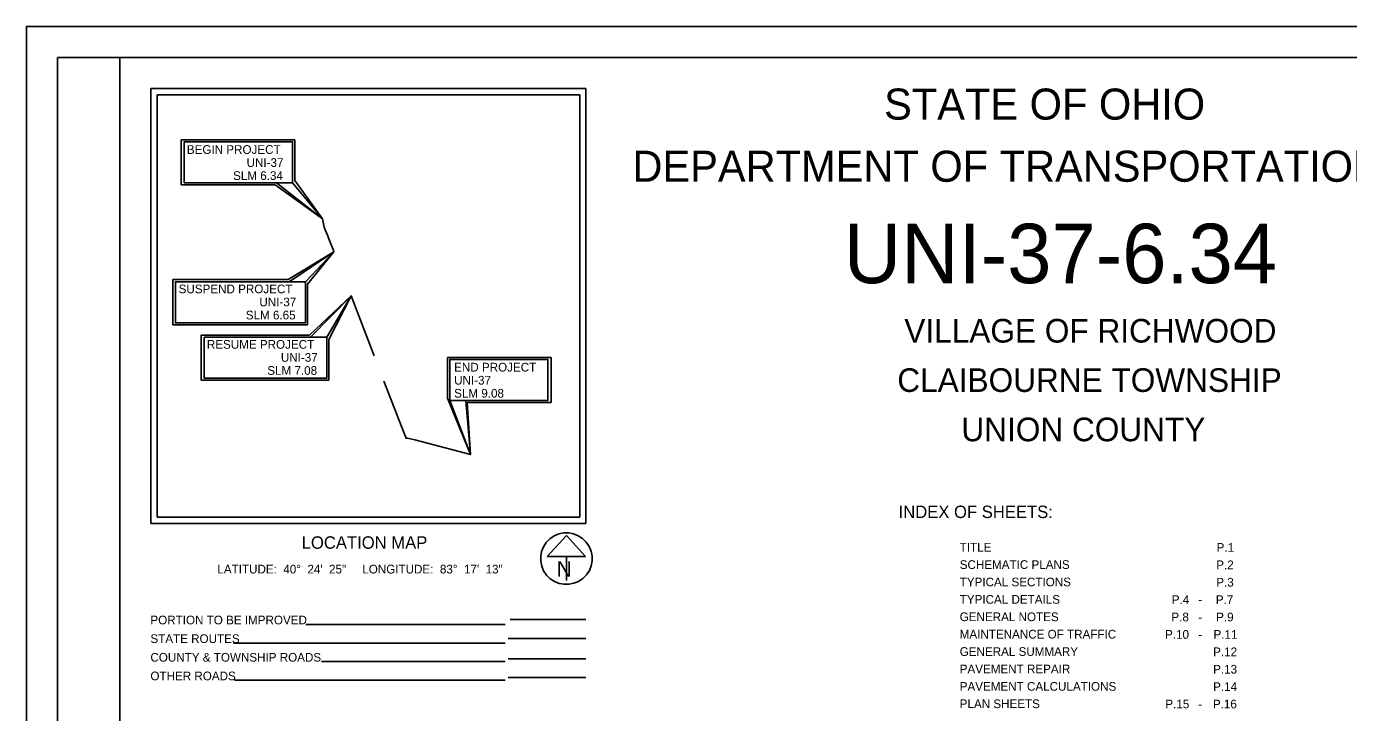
# Model space of a CAD drawing. Extents: x 0 to 34, y 0 to 22.
# Drawn here: x 0 to 21.27, y 10.96 to 22 of the extents above; entities that cross this region are included whole.
import ezdxf

# ---------------------------------------------------------------- set-up
doc = ezdxf.new("R2010")
doc.units = 0
for name, color, linetype in [('GM_X_Interstate_Route', 7, 'Continuous'), ('GM_X_Interstate_Shield', 7, 'Continuous'), ('Level 62', 7, 'Continuous'), ('SC_Scratch7', 7, 'Continuous'), ('SC_Scratch9', 7, 'Continuous'), ('SH_Border', 7, 'Continuous'), ('SH_Cut_Line', 7, 'Continuous'), ('SH_Data', 7, 'Continuous')]:
    doc.layers.add(name, color=color, linetype=linetype)

msp = doc.modelspace()

# ---------------------------------------------------------------- linework, layer by layer
at = {"layer": 'GM_X_Interstate_Route'}
msp.add_line((9, 12.149), (7.75, 12.149), dxfattribs=at)
at = {"layer": 'GM_X_Interstate_Shield'}
msp.add_line((9, 11.522), (7.75, 11.522), dxfattribs=at)
at = {"layer": 'Level 62'}
msp.add_line((9, 11.822), (7.75, 11.822), dxfattribs=at)
at = {"layer": 'SC_Scratch7'}
for p, q in [((2.488, 19.449), (2.488, 20.177)), ((2.488, 20.177), (4.315, 20.177)), ((4.315, 20.177), (4.315, 19.521)), ((4.002, 19.449), (2.488, 19.449)), ((4.76, 18.901), (4.002, 19.449)), ((4.315, 19.521), (4.76, 18.901)), ((4.945, 18.374), (4.207, 17.925)), ((4.521, 17.853), (4.945, 18.374)), ((4.207, 17.925), (2.357, 17.925)), ((2.357, 17.925), (2.357, 17.197)), ((4.521, 17.197), (4.521, 17.853)), ((5.225, 17.664), (4.552, 17.033)), ((4.866, 16.962), (5.225, 17.664)), ((2.357, 17.197), (4.521, 17.197)), ((4.552, 17.033), (2.809, 17.033)), ((2.809, 17.033), (2.809, 16.305)), ((4.866, 16.305), (4.866, 16.962)), ((8.442, 16.674), (6.775, 16.674)), ((6.775, 16.674), (6.775, 16.018)), ((8.442, 15.946), (8.442, 16.674)), ((2.809, 16.305), (4.866, 16.305)), ((6.775, 16.018), (7.14, 15.109)), ((7.14, 15.109), (7.088, 15.946)), ((7.088, 15.946), (8.442, 15.946))]:
    msp.add_line(p, q, dxfattribs=at)
at = {"layer": 'SH_Border'}
msp.add_lwpolyline([(0, 0), (34, 0), (34, 22), (0, 22)], close=True, dxfattribs=at)
at = {"layer": 'SH_Cut_Line'}
for p, q in [((2, 21), (9, 21)), ((2, 21), (2, 14)), ((2.1, 20.9), (2.1, 14.1)), ((2.1, 20.9), (8.9, 20.9)), ((8.9, 20.9), (8.9, 14.1)), ((9, 21), (9, 14)), ((5.225, 17.664), (5.593, 16.701)), ((2.1, 14.1), (8.9, 14.1)), ((2.1, 14.1), (2.1, 14.1)), ((2, 14), (9, 14)), ((8.685, 13.809), (8.377, 13.468)), ((8.992, 13.468), (8.685, 13.809)), ((8.377, 13.468), (8.992, 13.468)), ((8.685, 13.468), (8.685, 13.081)), ((8.685, 13.435), (8.685, 13.435)), ((8.685, 13.435), (8.685, 13.435)), ((7.7, 12.377), (4.494, 12.377)), ((7.783, 12.455), (9, 12.455)), ((7.7, 12.077), (3.329, 12.077)), ((7.7, 11.777), (4.745, 11.777)), ((7.7, 11.477), (3.347, 11.477))]:
    msp.add_line(p, q, dxfattribs=at)
for points in [[(4.281, 19.483), (2.537, 19.483), (2.537, 20.144), (4.281, 20.144)], [(4.021, 19.483), (4.76, 18.901), (4.281, 19.483)], [(4.227, 17.89), (4.945, 18.374), (4.487, 17.89)], [(4.487, 17.89), (2.396, 17.89), (2.396, 17.229), (4.487, 17.229)], [(4.571, 16.999), (5.225, 17.664), (4.831, 16.999)], [(4.831, 16.999), (2.861, 16.999), (2.861, 16.338), (4.831, 16.338)], [(6.809, 15.981), (8.387, 15.981), (8.387, 16.642), (6.809, 16.642)], [(7.069, 15.981), (7.14, 15.109), (6.809, 15.981)]]:
    msp.add_lwpolyline(points, close=True, dxfattribs=at)
for points in [[(4.76, 18.901), (4.765, 18.879), (4.789, 18.772), (4.796, 18.753), (4.842, 18.638), (4.863, 18.583), (4.931, 18.412), (4.945, 18.374)], [(5.751, 16.292), (6.043, 15.537), (6.106, 15.371), (6.129, 15.376), (6.249, 15.346), (7.14, 15.109)]]:
    msp.add_lwpolyline(points, dxfattribs=at)
msp.add_arc((8.685, 13.435), 0.415, 129.7798, 129.7633, dxfattribs=at)
at = {"layer": 'SH_Data'}
for points in [[(0.5, 21.5), (1.5, 21.5), (1.5, 0.5), (0.5, 0.5)], [(1.5, 21.5), (33.5, 21.5), (33.5, 0.5), (1.5, 0.5)]]:
    msp.add_lwpolyline(points, close=True, dxfattribs=at)

# ---------------------------------------------------------------- texts
at = {"layer": 'SC_Scratch9'}
for s, height, p in [('STATE OF OHIO', 0.5, (13.795, 20.5)), ('DEPARTMENT OF TRANSPORTATION', 0.5, (9.747, 19.5)), ('UNI-37-6.34', 0.95673, (13.146, 17.868)), ('VILLAGE OF RICHWOOD', 0.38, (14.12, 16.912)), ('CLAIBOURNE TOWNSHIP', 0.38, (14.007, 16.118)), ('UNION COUNTY', 0.38, (15.038, 15.324)), ('INDEX OF SHEETS:', 0.2, (14.028, 14.088)), ('LOCATION MAP', 0.2, (4.427, 13.594)), ('LATITUDE:  40°  24\'  25"     LONGITUDE:  83°  17\'  13"', 0.14, (3.071, 13.196)), ('PORTION TO BE IMPROVED', 0.14, (1.994, 12.377)), ('STATE ROUTES', 0.14, (1.994, 12.077)), ('COUNTY & TOWNSHIP ROADS', 0.14, (1.994, 11.777)), ('OTHER ROADS', 0.14, (1.994, 11.477))]:
    msp.add_text(s, height=height, dxfattribs=at).set_placement(p)
at = {"layer": 'SH_Cut_Line'}
for s, height, p in [('BEGIN PROJECT', 0.14, (2.58, 19.949)), ('UNI-37', 0.14, (3.541, 19.739)), ('SLM 6.34', 0.14, (3.324, 19.529)), ('SUSPEND PROJECT', 0.14, (2.448, 17.705)), ('UNI-37', 0.14, (3.747, 17.495)), ('SLM 6.65', 0.14, (3.528, 17.285)), ('RESUME PROJECT', 0.14, (2.902, 16.813)), ('UNI-37', 0.14, (4.092, 16.603)), ('END PROJECT', 0.14, (6.879, 16.446)), ('SLM 7.08', 0.14, (3.874, 16.393)), ('UNI-37', 0.14, (6.879, 16.236)), ('SLM 9.08', 0.14, (6.879, 16.026)), ('TITLE', 0.14, (15.011, 13.549)), ('P.1', 0.14, (19.143, 13.545)), ('SCHEMATIC PLANS', 0.14, (15.011, 13.269)), ('P.2', 0.14, (19.137, 13.265)), ('N', 0.25, (8.529, 13.144)), ('TYPICAL SECTIONS', 0.14, (15.011, 12.989)), ('P.3', 0.14, (19.138, 12.985)), ('TYPICAL DETAILS', 0.14, (15.011, 12.709)), ('P.4', 0.14, (18.422, 12.705)), ('-', 0.14, (18.846, 12.705)), ('P.7', 0.14, (19.131, 12.705)), ('GENERAL NOTES', 0.14, (15.011, 12.429)), ('P.8', 0.14, (18.416, 12.425)), ('P.9', 0.14, (19.135, 12.425)), ('-', 0.14, (18.846, 12.425)), ('MAINTENANCE OF TRAFFIC', 0.14, (15.011, 12.149)), ('P.10', 0.14, (18.314, 12.145)), ('-', 0.14, (18.846, 12.145)), ('P.11', 0.14, (19.093, 12.145)), ('GENERAL SUMMARY', 0.14, (15.011, 11.869)), ('P.12', 0.14, (19.087, 11.865)), ('PAVEMENT REPAIR', 0.14, (15.011, 11.589)), ('P.13', 0.14, (19.087, 11.585)), ('PAVEMENT CALCULATIONS', 0.14, (15.011, 11.309)), ('P.14', 0.14, (19.087, 11.305)), ('PLAN SHEETS', 0.14, (15.011, 11.029)), ('P.15', 0.14, (18.318, 11.025)), ('-', 0.14, (18.846, 11.025)), ('P.16', 0.14, (19.083, 11.025))]:
    msp.add_text(s, height=height, dxfattribs=at).set_placement(p)

doc.saveas('drawing.dxf')
